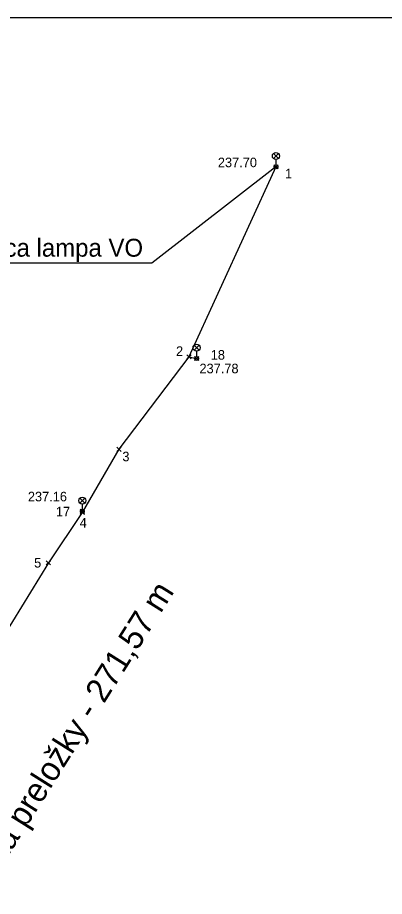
# Model space of a CAD drawing. Extents: x -263861 to -263441, y -1242367 to -1242070.
# Drawn here: x -263732.4 to -263655.6, y -1242254.1 to -1242070.2 of the extents above; entities that cross this region are included whole.
import ezdxf

# ---------------------------------------------------------------- set-up
doc = ezdxf.new("R2010")
doc.units = 0
for name, color, linetype in [('KFA_BODY', 7, 'Continuous'), ('KFA_VO_prelozka_pri_vjazde_do KFA_LAMPA', 7, 'Continuous'), ('KFA_VO_prelozka_pri_vjazde_do KFA_LAMPA_JESTVUJUCA', 7, 'Continuous'), ('KFA_VO_prelozka_pri_vjazde_do KFA_TRASA', 7, 'Continuous'), ('POPIS', 7, 'Continuous'), ('RAM_NA_TLAC_A3_1-1000', 7, 'Continuous')]:
    doc.layers.add(name, color=color, linetype=linetype)

msp = doc.modelspace()

# ---------------------------------------------------------------- linework, layer by layer
at = {"layer": 'KFA_BODY'}
for p, q in [((-263678.79, -1242101.86), (-263677.91, -1242100.98)), ((-263677.91, -1242101.86), (-263678.79, -1242100.98)), ((-263678.35, -1242101.42), (-263678.35, -1242101.42)), ((-263697.01, -1242141.63), (-263696.12, -1242140.74)), ((-263696.12, -1242141.63), (-263697.01, -1242140.74)), ((-263696.56, -1242141.18), (-263696.56, -1242141.18)), ((-263695.39, -1242141.97), (-263694.51, -1242141.08)), ((-263694.51, -1242141.97), (-263695.39, -1242141.08)), ((-263694.95, -1242141.52), (-263694.95, -1242141.52)), ((-263711.66, -1242160.97), (-263710.77, -1242160.09)), ((-263710.77, -1242160.97), (-263711.66, -1242160.09)), ((-263711.21, -1242160.53), (-263711.21, -1242160.53)), ((-263719.33, -1242174.16), (-263718.44, -1242173.27)), ((-263718.44, -1242174.16), (-263719.33, -1242173.27)), ((-263719.31, -1242173.96), (-263718.43, -1242173.07)), ((-263718.43, -1242173.96), (-263719.31, -1242173.07)), ((-263718.89, -1242173.72), (-263718.87, -1242173.52)), ((-263718.89, -1242173.72), (-263718.89, -1242173.72)), ((-263718.87, -1242173.52), (-263718.87, -1242173.52)), ((-263726.41, -1242184.71), (-263725.53, -1242183.83)), ((-263725.53, -1242184.71), (-263726.41, -1242183.83)), ((-263725.97, -1242184.27), (-263725.97, -1242184.27))]:
    msp.add_line(p, q, dxfattribs=at)
at = {"layer": 'KFA_VO_prelozka_pri_vjazde_do KFA_LAMPA'}
for p, q in [((-263695.48, -1242139.8), (-263694.42, -1242138.74)), ((-263695.48, -1242138.74), (-263694.42, -1242139.8)), ((-263694.95, -1242140.02), (-263694.95, -1242141.12)), ((-263719.4, -1242171.79), (-263718.34, -1242170.74)), ((-263719.4, -1242170.74), (-263718.34, -1242171.79)), ((-263718.87, -1242172.02), (-263718.87, -1242173.11))]:
    msp.add_line(p, q, dxfattribs=at)
for centre, radius in [((-263694.95, -1242139.27), 0.75), ((-263694.95, -1242141.52), 0.4), ((-263718.87, -1242171.27), 0.75), ((-263718.87, -1242173.52), 0.4)]:
    msp.add_circle(centre, radius, dxfattribs=at)
at = {"layer": 'KFA_VO_prelozka_pri_vjazde_do KFA_LAMPA_JESTVUJUCA'}
for p, q in [((-263678.88, -1242099.7), (-263677.82, -1242098.64)), ((-263678.88, -1242098.64), (-263677.82, -1242099.7)), ((-263678.35, -1242099.92), (-263678.35, -1242101.02))]:
    msp.add_line(p, q, dxfattribs=at)
for centre, radius in [((-263678.35, -1242099.17), 0.75), ((-263678.35, -1242101.42), 0.4)]:
    msp.add_circle(centre, radius, dxfattribs=at)
at = {"layer": 'KFA_VO_prelozka_pri_vjazde_do KFA_TRASA'}
msp.add_line((-263696.56, -1242141.18), (-263694.95, -1242141.52), dxfattribs=at)
msp.add_lwpolyline([(-263678.35, -1242101.42), (-263696.56, -1242141.18), (-263711.21, -1242160.53), (-263718.89, -1242173.72), (-263725.97, -1242184.27), (-263742.99, -1242211.9), (-263755.73, -1242230.93), (-263756.36, -1242233.15), (-263759.75, -1242241.52), (-263769.7, -1242254.93), (-263792.51, -1242289.19), (-263819.79, -1242330.66), (-263820.54, -1242331.86)], dxfattribs=at)
at = {"layer": 'POPIS'}
for p, q in [((-263678.35, -1242101.42), (-263704.29, -1242121.59)), ((-263704.29, -1242121.59), (-263753.53, -1242121.59))]:
    msp.add_line(p, q, dxfattribs=at)
at = {"layer": 'RAM_NA_TLAC_A3_1-1000'}
msp.add_lwpolyline([(-263861.44, -1242070.21), (-263441.44, -1242070.21), (-263441.44, -1242367.21), (-263861.44, -1242367.21)], close=True, dxfattribs=at)

# ---------------------------------------------------------------- texts
at = {"layer": 'KFA_BODY'}
for s, p in [('237.70', (-263690.5, -1242101.51)), ('1', (-263676.45, -1242103.84)), ('2', (-263699.26, -1242140.99)), ('18', (-263691.99, -1242141.77)), ('237.78', (-263694.35, -1242144.62)), ('3', (-263710.49, -1242163.03)), ('237.16', (-263730.26, -1242171.42)), ('17', (-263724.39, -1242174.56)), ('4', (-263719.42, -1242176.89)), ('5', (-263728.95, -1242185.27))]:
    msp.add_text(s, height=2, dxfattribs=at).set_placement(p)
at = {"layer": 'POPIS'}
msp.add_text('jestvujúca lampa VO', height=3.75, dxfattribs=at).set_placement((-263752.14, -1242120.23))
msp.add_text('trasa VO, dĺžka preložky - 271,57 m', height=5, rotation=57.838, dxfattribs=at).set_placement((-263756.08, -1242280.23))

doc.saveas('drawing.dxf')
